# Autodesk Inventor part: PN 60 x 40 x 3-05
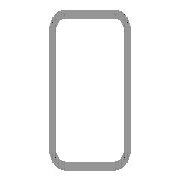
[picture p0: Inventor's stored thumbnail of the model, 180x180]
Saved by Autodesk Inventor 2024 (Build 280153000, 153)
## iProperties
_CCFamilyMember: 10
_CCFamilyDisplayName: PN EN 10219-2 (Profil walcowany, prostokątny - kształtowany na zimno) - Konstrukcyjne profile wydrążone ze stali węglowej i drobnoziarnistej, spawane, kształtow
_FrameMemberDoc: Frame Member File
_Version: 15.0.0
Company: ATC
Created: 2023-03
Part Number: PN 60 x 40 x 3-05
Material: Ogólny
Description: Konstrukcyjne profile wydrążone ze stali węglowej i drobnoziarnistej, spawane, kształtowane na zimno
Document SubType Name: Modeling
Standard: PN EN 10219-2
Designer: Andrzej Jaskulski
Standards Organization: PN
Language: pl-PL
Size Designation: 60 x 40 x 3
Categories: <MemberInstance><Categories><Category DisplayName="Kształtowniki konstrukcyjne" InternalName="089c4875-fa83-4c05-b084-43b9cc11f5ed" Mnemonic="GRDR"><CategoryPar
Stock Number: 60 x 40 x 3
Density: 1 g/cm^3
Appearance: Domyślna
Checked By: A.J.
Engr Approved By: Andrzej Jaskulski
Mfg Approved By: Andrzej Jaskulski
Authority: A.J.
IsCustomPart: 1
G_L: 240,000 mm
G_W: 40,000 mm
G_H: 60,000 mm
+78594D8E-C42A-4ECC-B0AF-A7D280CED65D+CUTDETAIL1: Połączenie narożne
+50356EDF-CAC9-44D9-8C18-2E8D81CB3D2A+CUTDETAIL2: Połączenie narożne
Author: Andrzej Jaskulski
Title: A.J.: Kurs R2024-MEP
Revision Number: 1/24
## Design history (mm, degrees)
node "Płaszczyzna początkowa"
node "Płaszczyzna końcowa"
sketch "Szkic"
  geometry: L1 (-20, -24)-(-20, 24); L2 (-14, 30)-(14, 30); L3 (20, 24)-(20, -24); L4 (14, -30)-(-14, -30); L5 (-14, 27)-(14, 27); L6 (17, 24)-(17, -24); L7 (14, -27)-(-14, -27); L8 (-17, -24)-(-17, 24); L9 (0, 43.74)-(0, -43.74) reference; L10 (-29.74, 0)-(29.74, 0) reference; A1 r 6 centre (-14, -24) between (-20, -24) and (-14, -30); A2 r 6 centre (-14, 24) between (-14, 30) and (-20, 24); A3 r 6 centre (14, 24) between (20, 24) and (14, 30); A4 r 6 centre (14, -24) between (14, -30) and (20, -24); A5 r 3 centre (-14, 24) between (-14, 27) and (-17, 24); A6 r 3 centre (14, 24) between (17, 24) and (14, 27); A7 r 3 centre (14, -24) between (14, -27) and (17, -24); A8 r 3 centre (-14, -24) between (-17, -24) and (-14, -27)
  constraints: 16 end point, 16 point on circle, 8 centre point, 8 tangent, 4 parallel, 3 equal radius, 2 perpendicular, 7 other
  dimensions: "d7" = 6 radius of A1 (= G_IR); "d10" = 60 distance between parallel lines of L2 L4 (= G_H); "d11" = 40 distance between parallel lines of L1 L3 (= G_W); "d12" = 3 distance between parallel lines of L3 L6 (= G_T); "d15" = 30 distance between parallel lines of L2 L10 (= 0.5 x d10); "d16" = 20 distance between parallel lines of L9 L3 (= 0.5 x d11)
extrude "Bryła" new body sketch "Szkic" stored distance "d3" = 240 (= G_L); taper "d4" = 0 deg
node "Driven Length"
  sketch "Sketch3"
    geometry: L1 (0, 0)-(10, 0) reference
    constraints: 2 end point, 1 horizontal
  workplane "Work Plane3"
node "Płaszczyzna konstrukcyjna4"
feature "Podział1"
node "Płaszczyzna konstrukcyjna5"
feature "Podział2"
node "Otwory1"
node "Otwory2"
body "Solid1"
sketch "Sketch4"
  geometry: L1 (-2, 0)-(12, 0) reference; L2 (-2, 240)-(12, 240) reference
  dimensions: "d18" = 240 distance between parallel lines of L1 L2 (derived)
sketch "Szkic5"
  geometry: 1 further point
hole "Otwór1" sketch "Szkic5" diameter "d19" = 22; stored, may be unused: countersink angle "d23" = 90 deg, drill point angle "d25" = 0 deg; dims "d20" = 6, "d21" = 4, "d22" = 2, "d24" = 8
sketch "Szkic6"
  geometry: 1 further point
hole "Otwór2" sketch "Szkic6" diameter "d26" = 22; stored, may be unused: countersink angle "d30" = 90 deg, drill point angle "d32" = 0 deg; dims "d27" = 6, "d28" = 4, "d29" = 2, "d31" = 8
other parameters: "G_W" = 40 [user parameter; used in 1 equation term], "G_H" = 60 [user parameter; used in 1 equation term], "G_T" = 3 [user parameter; used in 1 equation term], "G_IR" = 6 [user parameter; used in 1 equation term], "G_L" = 240 (= d18) [user parameter; used in 1 equation term], "G_OFFSET_START" = 0 [user parameter; used in 1 equation term], "G_OFFSET_END" = 0 [user parameter; used in 1 equation term], "d13" = 0 (computed from G_OFFSET_START), "d17" = 90 deg
